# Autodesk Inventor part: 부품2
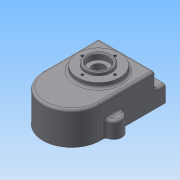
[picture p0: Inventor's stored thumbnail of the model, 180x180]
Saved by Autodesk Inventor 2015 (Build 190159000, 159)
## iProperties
Created: 2024-03
Part Number: 부품2
Material: 일반
Document SubType Name: Modeling
Designer: 학생용
Density: 1 g/cm^3
Appearance: 기본값
Author: 학생용
## Parameters: d1 = 68 mm, d4 = 0, d5 = 52 mm, d6 = 35 mm, d7 = 6 mm, d8 = 0, d9 = 32 mm, d10 = 4 mm, d11 = 0, d12 = 12 mm, d13 = 12 mm, d17 = 0, d20 = 63.5 mm, d21 = 63.5 mm, d23 = 0, d24 = 3 mm, d25 = 36 mm, d26 = 36 mm, d27 = 33 mm, d28 = 35 mm, d29 = 28 mm, d31 = 0, d33 = 21 mm, d34 = 3.242 mm, d35 = 8 mm, d36 = 3.023 mm, d37 = 2 mm, d38 = 82 deg, d40 = 118 deg, d42 = 360 deg, d51 = 7.3 mm, d53 = 25 mm, d54 = 15 mm, d55 = 90 deg, d58 = 0, d60 = 7 mm, d61 = 120 deg, d62 = 90 deg, d68 = 1 mm, d69 = 2 mm, d70 = 45 deg, d71 = 1 mm, d72 = 2 mm, d73 = 45 deg, d74 = 1 mm, d75 = 2 mm, d76 = 45 deg, d77 = 4 mm, d78 = 26 mm, d79 = 4 mm, d80 = 4 mm, d81 = 63.5 mm, d82 = 63.5 mm, d83 = 4 mm, d84 = 26.5 mm, d85 = 4.134 mm, d87 = 3.023 mm, d88 = 2 mm, d89 = 82 deg, d90 = 12 mm, d91 = 118 deg, d92 = 3 mm, d93 = 3 mm, d94 = 3 mm, d95 = 3 mm, d98 = 3 mm, d99 = 3 mm, d100 = 3 mm, d101 = 3 mm, d140 = 0.5 mm, d141 = 0, d143 = 63.5 mm, d144 = 6 mm, d146 = 11 mm, d147 = 0, d148 = 90 deg, d149 = 0, d150 = 0, d151 = 8 mm, d154 = 10.5 mm, d155 = 11 mm, d156 = 0.62479 mm, d157 = 10.589 mm, d158 = 3.023 mm, d159 = 2 mm, d160 = 82 deg, d161 = 16 mm, d162 = 118 deg, d165 = 10.5 mm, d166 = 11 mm, d167 = 0.62479 mm, d168 = 10.589 mm, d169 = 3.023 mm, d170 = 2 mm, d171 = 82 deg, d172 = 16 mm, d173 = 118 deg
